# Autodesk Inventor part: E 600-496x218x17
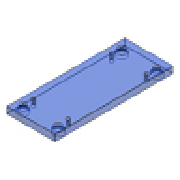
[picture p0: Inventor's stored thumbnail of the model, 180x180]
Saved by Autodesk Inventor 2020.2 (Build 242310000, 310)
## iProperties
Manager: www.cadconsulting.pl
Company: Fabian Stasiak CAD Consulting
Created: 2014-02
Part Number: E 600-496x218x17
Material: S 55 C
Description: Ejector Retainer Plate
Document SubType Name: Modeling
Designer: F.Stasiak
Standard Revision: 1
Manufacturer: DME
Language: pl-PL
Size Designation: 496x218x17
Categories: <MemberInstance><Categories><Category DisplayName="Forma wtryskowa" InternalName="349578f2-f4d4-4954-8c09-8e99297a61c0" Mnemonic="MOLD"><Category DisplayName="P
Density: 7.85 g/cm^3
Appearance: Clear - Blue
Catalog Web Link: www.expertbooks.pl
IsCustomPart: 1
Author: F.Stasiak
Subject: Zbiór ćwiczeń. Autodesk Inventor 2020. Kurs Professional
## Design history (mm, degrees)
sketch "Sketch1"
  geometry: L1 (-109, 248)-(109, 248); L2 (109, 248)-(109, -248); L3 (109, -248)-(-109, -248); L4 (-109, -248)-(-109, 248); 5 further points
  constraints: 8 end point, 2 midpoint, 2 parallel, 1 horizontal, 1 horizontal alignment, 1 perpendicular, 1 vertical alignment
  dimensions: "d84" = 218 distance between parallel lines of L2 L4 (= W_); "d85" = 496 distance between parallel lines of L3 L1 (= L); "d86" = 95 horizontal distance of point (0, 0) point (-95, 233) (= 0.5 x RP_W); "d87" = 233 vertical distance of point (0, 0) point (-95, 233) (= 0.5 x RP_L); "d88" = 95 horizontal distance of point (0, 0) point (-95, 210) (= 0.5 x S2_W); "d89" = 210 vertical distance of point (0, 0) point (-95, 210) (= 0.5 x S2_L)
extrude "Extrusion1" new body sketch "Sketch1" distance "d20" = 17 (= H_); taper "d30" = 0 deg
hole "Hole1" sketch "Sketch1" diameter "d90" = 8.376; stored, may be unused: countersink angle "d94" = 90 deg, drill point angle "d96" = 0 deg; dims "d91" = 6, "d92" = 4, "d93" = 2, "d95" = 17 (= H_)
pattern_linear "Rectangular Pattern1" dims "d106" = 420 (computed from S2_L, Nl), "d109" = 190 (computed from S2_W, Nw)
hole "Hole2" sketch "Sketch1" diameter "d97" = 14 (= RP_d1); stored, may be unused: countersink angle "d101" = 90 deg, drill point angle "d103" = 0 deg; dims "d98" = 6, "d99" = 19 (= RP_d2), "d100" = 4 (= RP_k), "d102" = 17 (= H_)
pattern_linear "Rectangular Pattern2" dims "d112" = 466 (computed from RP_L, Nl), "d115" = 190 (computed from RP_W, Nw)
chamfer "Chamfer1" distance "d116" = 0.5; stored, may be unused: second distance "d117" = 2, angle "d118" = 45 deg
sketch "Szkic13"
  geometry: 1 further point
hole "Otwór19" sketch "Szkic13" at (0, 0) diameter "d196" = 4.5; stored, may be unused: countersink angle "d200" = 90 deg, drill point angle "d202" = 0 deg; dims "d197" = 6, "d198" = 8, "d199" = 3, "d201" = 8
sketch "Szkic14"
  geometry: 4 further points
hole "Otwór20" sketch "Szkic14" at (-54, 134), (-24, -134), (24, 134), (54, -134) diameter "d203" = 5; stored, may be unused: countersink angle "d207" = 90 deg, drill point angle "d209" = 0 deg; dims "d204" = 6, "d205" = 9, "d206" = 3, "d208" = 8
sketch "Szkic15"
  geometry: 4 further points
hole "Otwór21" sketch "Szkic15" at (-24, 134), (-54, -134), (54, 134), (24, -134) diameter "d210" = 5; stored, may be unused: countersink angle "d214" = 90 deg, drill point angle "d216" = 0 deg; dims "d211" = 6, "d212" = 9, "d213" = 3, "d215" = 8
sketch "Szkic16"
  geometry: 4 further points
hole "Otwór22" sketch "Szkic16" at (-54, 103.5), (-24, -103.5), (24, 103.5), (54, -103.5) diameter "d217" = 5; stored, may be unused: countersink angle "d221" = 90 deg, drill point angle "d223" = 0 deg; dims "d218" = 6, "d219" = 9, "d220" = 3, "d222" = 8
sketch "Szkic17"
  geometry: 4 further points
hole "Otwór23" sketch "Szkic17" at (-24, 103.5), (-54, -103.5), (54, 103.5), (24, -103.5) diameter "d224" = 5; stored, may be unused: countersink angle "d228" = 90 deg, drill point angle "d230" = 0 deg; dims "d225" = 6, "d226" = 9, "d227" = 3, "d229" = 8
sketch "Szkic18"
  geometry: 4 further points
hole "Otwór24" sketch "Szkic18" at (-47, 71.2), (-31, -71.2), (31, 71.2), (47, -71.2) diameter "d231" = 5; stored, may be unused: countersink angle "d235" = 90 deg, drill point angle "d237" = 0 deg; dims "d232" = 6, "d233" = 9, "d234" = 3, "d236" = 8
sketch "Szkic19"
  geometry: 4 further points
hole "Otwór25" sketch "Szkic19" at (-31, 71.2), (-47, -71.2), (47, 71.2), (31, -71.2) diameter "d238" = 5; stored, may be unused: countersink angle "d242" = 90 deg, drill point angle "d244" = 0 deg; dims "d239" = 6, "d240" = 9, "d241" = 3, "d243" = 8
sketch "Szkic20"
  geometry: 4 further points
hole "Otwór26" sketch "Szkic20" at (-48.5, 54), (-29.5, -54), (29.5, 54), (48.5, -54) diameter "d245" = 5; stored, may be unused: countersink angle "d249" = 90 deg, drill point angle "d251" = 0 deg; dims "d246" = 6, "d247" = 9, "d248" = 3, "d250" = 8
sketch "Szkic21"
  geometry: 4 further points
hole "Otwór27" sketch "Szkic21" at (-29.5, 54), (-48.5, -54), (48.5, 54), (29.5, -54) diameter "d252" = 5; stored, may be unused: countersink angle "d256" = 90 deg, drill point angle "d258" = 0 deg; dims "d253" = 6, "d254" = 9, "d255" = 3, "d257" = 8
sketch "Szkic22"
  geometry: 4 further points
hole "Otwór28" sketch "Szkic22" at (-57, 29), (-21, -29), (21, 29), (57, -29) diameter "d259" = 5; stored, may be unused: countersink angle "d263" = 90 deg, drill point angle "d265" = 0 deg; dims "d260" = 6, "d261" = 9, "d262" = 3, "d264" = 8
sketch "Szkic23"
  geometry: 4 further points
hole "Otwór29" sketch "Szkic23" at (-39, 35), (-39, -35), (39, 35), (39, -35) diameter "d266" = 5; stored, may be unused: countersink angle "d270" = 90 deg, drill point angle "d272" = 0 deg; dims "d267" = 6, "d268" = 9, "d269" = 3, "d271" = 8
sketch "Szkic24"
  geometry: 4 further points
hole "Otwór30" sketch "Szkic24" at (-21, 29), (-57, -29), (57, 29), (21, -29) diameter "d273" = 5; stored, may be unused: countersink angle "d277" = 90 deg, drill point angle "d279" = 0 deg; dims "d274" = 6, "d275" = 9, "d276" = 3, "d278" = 8
body "Solid1"
other parameters: "L" = 496 [user parameter; used in 1 equation term], "W_" = 218 [user parameter; used in 1 equation term], "H_" = 17 [user parameter; used in 3 equation terms], "RP_k" = 4 [user parameter; used in 1 equation term], "RP_d1" = 14 [user parameter; used in 1 equation term], "RP_d2" = 19 [user parameter; used in 1 equation term], "RP_L" = 466 [user parameter; used in 2 equation terms]
